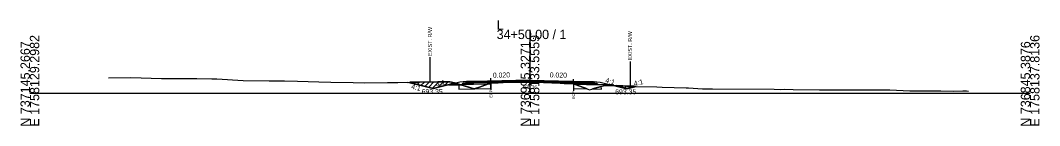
# Model space of a CAD drawing. Extents: x -26 to 4303, y -10 to 9577.
# Drawn here: x 1997.2 to 2302.8, y 4490.3 to 4521.9 of the extents above; entities that cross this region are included whole.
import ezdxf

# ---------------------------------------------------------------- set-up
doc = ezdxf.new("R2010")
doc.units = 0
for name, color, linetype in [('Default', 7, 'Continuous'), ('Exist CMT Pavement', 7, 'Continuous'), ('Old_Level_2', 7, 'Continuous'), ('Pattern 1', 7, 'Continuous'), ('Prop CMT Conc Surface', 7, 'Continuous'), ('Prop CMT Concrete Structures', 7, 'Continuous'), ('Prop CMT Pvmt Course 1', 7, 'Continuous'), ('Prop CMT Pvmt Course 1 CG', 7, 'Continuous'), ('Prop CMT Pvmt Course 1 Wedge', 7, 'Continuous'), ('Prop CMT Pvmt Course 2', 7, 'Continuous'), ('Prop CMT Pvmt Course 2 Wedge', 7, 'Continuous'), ('Prop CMT Pvmt Course 3', 7, 'Continuous'), ('Prop CMT Pvmt Surface', 7, 'Continuous'), ('Prop CMT Pvmt Surface Shoulder', 7, 'Continuous'), ('Prop CMT Pvmt Wedge Surface 1', 7, 'Continuous'), ('Prop CMT Pvmt Wedge Surface 2', 7, 'Continuous'), ('Prop CMT Pvmt Wedge Surface 3', 7, 'Continuous'), ('Prop CMT Shld Paved Course 1', 7, 'Continuous'), ('Prop CMT Shld Paved Course 2', 7, 'Continuous'), ('Prop CMT Shld Paved Course 3', 7, 'Continuous'), ('Prop CMT Slope Grass', 7, 'Continuous'), ('Prop CMT Subgrade Earthwork', 7, 'Continuous'), ('Prop Road Sect_ Recs - UC Shallow (Outline)', 7, 'Continuous'), ('Prop Shade Light', 7, 'Continuous'), ('Prop XS DDE Elevations', 7, 'Continuous'), ('Prop XS Ditch Standard Text', 7, 'Continuous'), ('Prop XS Hydro Elevations', 7, 'Continuous'), ('Prop XS SE Text', 7, 'Continuous'), ('Prop XS Side Slope Text', 7, 'Continuous'), ('Prop XS Wedging', 7, 'Continuous')]:
    doc.layers.add(name, color=color, linetype=linetype)

msp = doc.modelspace()

# ---------------------------------------------------------------- linework, layer by layer
at = {"layer": 'Exist CMT Pavement'}
for points in [[(2150, 4503.89), (2133, 4503.55)], [(2150, 4503.89), (2167, 4503.55)]]:
    msp.add_lwpolyline(points, dxfattribs=at)
at = {"layer": 'Old_Level_2'}
for p, q in [((2150, 4500), (2150, 4519.06)), ((2150, 4500), (2150, 4519.06)), ((2000, 4500), (2150, 4500)), ((2000, 4500), (2150, 4500)), ((2150, 4500), (2300, 4500)), ((2150, 4500), (2300, 4500))]:
    msp.add_line(p, q, dxfattribs=at)
at = {"layer": 'Pattern 1'}
for p, q in [((2113.99, 4503.27), (2114.01, 4503.29)), ((2115.12, 4502.99), (2115.45, 4503.32)), ((2116.25, 4502.71), (2116.89, 4503.34)), ((2117.38, 4502.42), (2118.32, 4503.36)), ((2118.51, 4502.14), (2119.76, 4503.38)), ((2119.65, 4501.86), (2121.19, 4503.4)), ((2120.78, 4501.57), (2122.62, 4503.42)), ((2122.51, 4501.9), (2124.05, 4503.43)), ((2124.4, 4502.37), (2125.47, 4503.44)), ((2126.15, 4502.71), (2126.71, 4503.27)), ((2127.6, 4502.74), (2127.85, 4502.99)), ((2176.2, 4502.22), (2176.27, 4502.29)), ((2177.33, 4501.94), (2177.63, 4502.24)), ((2178.46, 4501.65), (2178.99, 4502.18)), ((2179.98, 4501.77), (2180.34, 4502.13))]:
    msp.add_line(p, q, dxfattribs=at)
for points in [[(2121, 4501.52), (2125.72, 4502.7), (2128.66, 4502.76), (2127.39, 4503.12), (2125.95, 4503.44), (2122.32, 4503.42), (2116.49, 4503.34), (2113.92, 4503.29)], [(2137.78, 4502.94), (2138.29, 4503.12), (2138.29, 4502.95)], [(2175.84, 4502.31), (2179, 4501.52), (2181.28, 4502.09), (2179.79, 4502.15), (2177.85, 4502.23)]]:
    msp.add_lwpolyline(points, close=True, dxfattribs=at)
at = {"layer": 'Prop CMT Conc Surface'}
for points in [[(2138.29, 4503.41), (2133, 4503.3)], [(2133, 4503.3), (2133, 4503.09)], [(2133, 4503.09), (2138.29, 4503.2)], [(2138.29, 4503.2), (2138.29, 4503.41)], [(2163.07, 4503.17), (2163.07, 4503.38)], [(2163.07, 4503.38), (2167, 4503.3)], [(2167, 4503.09), (2163.07, 4503.17)], [(2167, 4503.3), (2167, 4503.09)]]:
    msp.add_lwpolyline(points, dxfattribs=at)
at = {"layer": 'Prop CMT Concrete Structures'}
for points in [[(2133, 4503.3), (2133, 4503.55)], [(2138.29, 4503.41), (2133, 4503.3)], [(2150, 4503.77), (2138.29, 4503.53)], [(2138.29, 4503.53), (2138.29, 4503.41)], [(2150, 4503.77), (2163.07, 4503.51)], [(2163.07, 4503.51), (2163.07, 4503.38)], [(2163.07, 4503.38), (2167, 4503.3)], [(2167, 4503.3), (2167, 4503.55)]]:
    msp.add_lwpolyline(points, dxfattribs=at)
at = {"layer": 'Prop CMT Pvmt Course 1'}
for points in [[(2138.29, 4503.2), (2133, 4503.09)], [(2133, 4503.09), (2133, 4502.76)], [(2133, 4502.76), (2138.29, 4502.87)], [(2138.29, 4502.87), (2138.29, 4503.2)], [(2163.07, 4503.17), (2167, 4503.09)], [(2163.07, 4502.84), (2163.07, 4503.17)], [(2167, 4502.76), (2163.07, 4502.84)], [(2167, 4503.09), (2167, 4502.76)]]:
    msp.add_lwpolyline(points, dxfattribs=at)
at = {"layer": 'Prop CMT Pvmt Course 1 Wedge'}
for points in [[(2138.29, 4503.2), (2138.39, 4503.2), (2138.75, 4503.21), (2138.88, 4503.21), (2139.95, 4503.23), (2140.5, 4503.24), (2141.57, 4503.27), (2142, 4503.27), (2144.07, 4503.32), (2144.43, 4503.32), (2146.58, 4503.37), (2146.86, 4503.37), (2149.08, 4503.42), (2149.13, 4503.42), (2149.55, 4503.43), (2149.78, 4503.43), (2150, 4503.43)], [(2150, 4503.36), (2149.78, 4503.36), (2149.55, 4503.35), (2149.13, 4503.34), (2149.08, 4503.34), (2146.86, 4503.33), (2146.58, 4503.33), (2144.43, 4503.29), (2144.07, 4503.29), (2142, 4503.21), (2141.57, 4503.2), (2140.5, 4503.18), (2139.95, 4503.17), (2138.88, 4503.15), (2138.75, 4503.16), (2138.39, 4503.16), (2138.29, 4503.12)], [(2138.29, 4503.12), (2138.29, 4503.2)], [(2150, 4503.43), (2150, 4503.36)], [(2150, 4503.43), (2150.44, 4503.43), (2151.28, 4503.41), (2151.55, 4503.4), (2151.58, 4503.4), (2151.72, 4503.4), (2154.08, 4503.35), (2154.15, 4503.35), (2156.58, 4503.3), (2156.59, 4503.3), (2156.84, 4503.3), (2159.02, 4503.25), (2159.08, 4503.25), (2160.22, 4503.23), (2160.74, 4503.22), (2161.92, 4503.2), (2163.03, 4503.17), (2163.06, 4503.17), (2163.07, 4503.17)], [(2163.07, 4502.79), (2163.06, 4502.8), (2163.03, 4502.8), (2161.92, 4502.92), (2160.74, 4502.96), (2160.22, 4502.96), (2159.08, 4503), (2159.02, 4503), (2156.84, 4503.12), (2156.59, 4503.13), (2156.58, 4503.13), (2154.15, 4503.24), (2154.08, 4503.25), (2151.72, 4503.32), (2151.58, 4503.33), (2151.55, 4503.33), (2151.28, 4503.34), (2150.44, 4503.36), (2150, 4503.36)], [(2163.07, 4503.17), (2163.07, 4502.79)]]:
    msp.add_lwpolyline(points, dxfattribs=at)
at = {"layer": 'Prop CMT Pvmt Course 2'}
for points in [[(2133, 4503.55), (2131, 4503.51), (2130.74, 4503.26)], [(2130.74, 4503.26), (2133, 4503.3)], [(2133, 4503.3), (2133, 4503.55)], [(2167, 4503.55), (2169, 4503.51), (2169.26, 4503.26)], [(2167, 4503.3), (2167, 4503.55)], [(2169.26, 4503.26), (2167, 4503.3)]]:
    msp.add_lwpolyline(points, dxfattribs=at)
at = {"layer": 'Prop CMT Pvmt Course 2 Wedge'}
for points in [[(2131, 4503.51), (2129, 4503.35), (2121, 4501.35), (2113.3, 4503.28)], [(2169, 4503.51), (2171, 4503.35), (2179, 4501.35), (2181.87, 4502.07)]]:
    msp.add_lwpolyline(points, dxfattribs=at)
at = {"layer": 'Prop CMT Pvmt Course 3'}
for points in [[(2133, 4503.3), (2130.74, 4503.26), (2130.53, 4503.05)], [(2130.53, 4503.05), (2133, 4503.09)], [(2133, 4503.09), (2133, 4503.3)], [(2167, 4503.3), (2169.26, 4503.26), (2169.47, 4503.05)], [(2167, 4503.09), (2167, 4503.3)], [(2169.47, 4503.05), (2167, 4503.09)]]:
    msp.add_lwpolyline(points, dxfattribs=at)
at = {"layer": 'Prop CMT Pvmt Surface'}
for points in [[(2150, 4503.64), (2133, 4503.3)], [(2133, 4503.3), (2133, 4503.55)], [(2150, 4503.64), (2167, 4503.3)], [(2167, 4503.3), (2167, 4503.55)]]:
    msp.add_lwpolyline(points, dxfattribs=at)
at = {"layer": 'Prop CMT Pvmt Surface Shoulder'}
for points in [[(2138.29, 4503.12), (2138.39, 4503.16), (2138.75, 4503.16), (2138.88, 4503.15), (2139.95, 4503.17), (2140.5, 4503.18), (2141.57, 4503.2), (2142, 4503.21), (2144.07, 4503.29), (2144.43, 4503.29), (2146.58, 4503.33), (2146.86, 4503.33), (2149.08, 4503.34), (2149.13, 4503.34), (2149.55, 4503.35), (2149.78, 4503.36), (2150, 4503.36)], [(2150, 4503.36), (2150.44, 4503.36), (2151.28, 4503.34), (2151.55, 4503.33), (2151.58, 4503.33), (2151.72, 4503.32), (2154.08, 4503.25), (2154.15, 4503.24), (2156.58, 4503.13), (2156.59, 4503.13), (2156.84, 4503.12), (2159.02, 4503), (2159.08, 4503), (2160.22, 4502.96), (2160.74, 4502.96), (2161.92, 4502.92), (2163.07, 4502.8)]]:
    msp.add_lwpolyline(points, dxfattribs=at)
at = {"layer": 'Prop CMT Pvmt Wedge Surface 1'}
for p, q in [((2138.29, 4502.74), (2133.02, 4502.64)), ((2163.07, 4502.71), (2166.98, 4502.64)), ((2133.02, 4502.64), (2125.53, 4502.49)), ((2166.98, 4502.64), (2174.47, 4502.49))]:
    msp.add_line(p, q, dxfattribs=at)
for points in [[(2138.29, 4502.74), (2138.29, 4503.12)], [(2163.07, 4502.8), (2163.07, 4502.71)]]:
    msp.add_lwpolyline(points, dxfattribs=at)
at = {"layer": 'Prop CMT Pvmt Wedge Surface 2'}
for points in [[(2138.29, 4503.53), (2138.39, 4503.54), (2138.75, 4503.54), (2138.88, 4503.55), (2139.95, 4503.57), (2140.5, 4503.58), (2141.57, 4503.6), (2142, 4503.61), (2144.07, 4503.65), (2144.43, 4503.66), (2146.58, 4503.7), (2146.86, 4503.7), (2149.08, 4503.75), (2149.13, 4503.75), (2149.55, 4503.76), (2149.78, 4503.76), (2150, 4503.77)], [(2150, 4503.64), (2149.78, 4503.64), (2149.55, 4503.63), (2149.13, 4503.63), (2149.08, 4503.62), (2146.86, 4503.58), (2146.58, 4503.57), (2144.43, 4503.53), (2144.07, 4503.52), (2142, 4503.48), (2141.57, 4503.47), (2140.5, 4503.45), (2139.95, 4503.44), (2138.88, 4503.42), (2138.75, 4503.42), (2138.39, 4503.41), (2138.29, 4503.41)], [(2138.29, 4503.41), (2138.29, 4503.53)], [(2150, 4503.77), (2150, 4503.64)], [(2150, 4503.77), (2150.44, 4503.76), (2151.28, 4503.74), (2151.55, 4503.74), (2151.58, 4503.74), (2151.72, 4503.73), (2154.08, 4503.69), (2154.15, 4503.68), (2156.58, 4503.64), (2156.59, 4503.64), (2156.84, 4503.63), (2159.02, 4503.59), (2159.08, 4503.59), (2160.22, 4503.56), (2160.74, 4503.55), (2161.92, 4503.53), (2163.03, 4503.51), (2163.06, 4503.51), (2163.07, 4503.51)], [(2163.07, 4503.38), (2163.06, 4503.38), (2163.03, 4503.38), (2161.92, 4503.4), (2160.74, 4503.43), (2160.22, 4503.44), (2159.08, 4503.46), (2159.02, 4503.46), (2156.84, 4503.51), (2156.59, 4503.51), (2156.58, 4503.51), (2154.15, 4503.56), (2154.08, 4503.56), (2151.72, 4503.61), (2151.58, 4503.61), (2151.55, 4503.61), (2151.28, 4503.62), (2150.44, 4503.63), (2150, 4503.64)], [(2163.07, 4503.51), (2163.07, 4503.38)]]:
    msp.add_lwpolyline(points, dxfattribs=at)
at = {"layer": 'Prop CMT Pvmt Wedge Surface 3'}
for points in [[(2138.29, 4503.41), (2138.39, 4503.41), (2138.75, 4503.42), (2138.88, 4503.42), (2139.95, 4503.44), (2140.5, 4503.45), (2141.57, 4503.47), (2142, 4503.48), (2144.07, 4503.52), (2144.43, 4503.53), (2146.58, 4503.57), (2146.86, 4503.58), (2149.08, 4503.62), (2149.13, 4503.63), (2149.55, 4503.63), (2149.78, 4503.64), (2150, 4503.64)], [(2150, 4503.43), (2149.78, 4503.43), (2149.55, 4503.43), (2149.13, 4503.42), (2149.08, 4503.42), (2146.86, 4503.37), (2146.58, 4503.37), (2144.43, 4503.32), (2144.07, 4503.32), (2142, 4503.27), (2141.57, 4503.27), (2140.5, 4503.24), (2139.95, 4503.23), (2138.88, 4503.21), (2138.75, 4503.21), (2138.39, 4503.2), (2138.29, 4503.2)], [(2138.29, 4503.2), (2138.29, 4503.41)], [(2150, 4503.64), (2150, 4503.43)], [(2150, 4503.64), (2150.44, 4503.63), (2151.28, 4503.62), (2151.55, 4503.61), (2151.58, 4503.61), (2151.72, 4503.61), (2154.08, 4503.56), (2154.15, 4503.56), (2156.58, 4503.51), (2156.59, 4503.51), (2156.84, 4503.51), (2159.02, 4503.46), (2159.08, 4503.46), (2160.22, 4503.44), (2160.74, 4503.43), (2161.92, 4503.4), (2163.03, 4503.38), (2163.06, 4503.38), (2163.07, 4503.38)], [(2163.07, 4503.17), (2163.06, 4503.17), (2163.03, 4503.17), (2161.92, 4503.2), (2160.74, 4503.22), (2160.22, 4503.23), (2159.08, 4503.25), (2159.02, 4503.25), (2156.84, 4503.3), (2156.59, 4503.3), (2156.58, 4503.3), (2154.15, 4503.35), (2154.08, 4503.35), (2151.72, 4503.4), (2151.58, 4503.4), (2151.55, 4503.4), (2151.28, 4503.41), (2150.44, 4503.43), (2150, 4503.43)], [(2163.07, 4503.38), (2163.07, 4503.17)]]:
    msp.add_lwpolyline(points, dxfattribs=at)
at = {"layer": 'Prop CMT Shld Paved Course 1'}
for points in [[(2133, 4503.09), (2133, 4503.55)], [(2150, 4503.43), (2133, 4503.09)], [(2150, 4503.43), (2167, 4503.09)], [(2167, 4503.09), (2167, 4503.55)]]:
    msp.add_lwpolyline(points, dxfattribs=at)
at = {"layer": 'Prop CMT Shld Paved Course 2'}
for points in [[(2133, 4503.55), (2131, 4503.51)], [(2167, 4503.55), (2169, 4503.51)]]:
    msp.add_lwpolyline(points, dxfattribs=at)
at = {"layer": 'Prop CMT Shld Paved Course 3'}
for points in [[(2150, 4503.89), (2133, 4503.55)], [(2133, 4503.55), (2133, 4503.3)], [(2133, 4503.3), (2138.29, 4503.41)], [(2138.29, 4503.53), (2150, 4503.77)], [(2138.29, 4503.41), (2138.29, 4503.53)], [(2150, 4503.64), (2150, 4503.89)], [(2150, 4503.89), (2167, 4503.55)], [(2150, 4503.77), (2150, 4503.64), (2150, 4503.64)], [(2163.07, 4503.51), (2150, 4503.77)], [(2163.07, 4503.38), (2163.07, 4503.51)], [(2167, 4503.3), (2163.07, 4503.38)], [(2167, 4503.55), (2167, 4503.3)]]:
    msp.add_lwpolyline(points, dxfattribs=at)
at = {"layer": 'Prop CMT Slope Grass'}
msp.add_lwpolyline([(2023.61, 4504.67), (2030.28, 4504.73), (2039.45, 4504.47), (2040.91, 4504.45), (2050.08, 4504.42), (2054.54, 4504.32), (2056.03, 4504.34), (2063.97, 4503.8), (2071.73, 4503.73), (2076.36, 4503.69), (2080.31, 4503.67), (2086.66, 4503.47), (2090.31, 4503.37), (2096.96, 4503.27), (2100.32, 4503.18), (2107.26, 4503.27), (2110.32, 4503.22), (2120.38, 4503.41), (2124.24, 4503.43), (2125.95, 4503.44), (2127.4, 4503.11), (2133.29, 4501.38), (2134.82, 4501.87), (2138.39, 4503.16), (2138.88, 4503.15), (2139.95, 4503.17), (2140.5, 4503.18), (2141.57, 4503.2), (2142, 4503.21), (2144.07, 4503.29), (2144.43, 4503.29), (2146.86, 4503.33), (2149.13, 4503.34), (2150, 4503.36), (2150.44, 4503.36), (2151.72, 4503.32), (2154.15, 4503.24), (2156.84, 4503.12), (2159.08, 4503), (2160.22, 4502.96), (2160.74, 4502.96), (2161.92, 4502.92), (2163.06, 4502.8), (2167.39, 4501.26), (2167.89, 4501.07), (2172.07, 4502.22), (2174.21, 4502.38), (2181.5, 4502.08), (2188.01, 4501.89), (2189.63, 4501.85), (2196.8, 4501.65), (2197.56, 4501.65), (2201.69, 4501.33), (2202.02, 4501.33), (2204.15, 4501.36), (2204.74, 4501.36), (2223.22, 4501.2), (2225.23, 4501.18), (2226.45, 4501.21), (2228.88, 4501.15), (2236.86, 4501.06), (2243.94, 4501.05), (2246.67, 4501.04), (2256.6, 4501.02), (2257.94, 4500.99), (2261.93, 4500.83), (2263.96, 4500.74), (2269.06, 4500.76), (2273.19, 4500.77), (2277.13, 4500.65), (2279.84, 4500.7), (2280.93, 4500.69), (2281.47, 4500.68)], dxfattribs=at)
at = {"layer": 'Prop CMT Subgrade Earthwork'}
for points in [[(2133, 4503.09), (2130.53, 4503.05), (2130.03, 4503.04), (2129.69, 4502.69)], [(2129.69, 4502.69), (2133, 4502.76)], [(2133, 4502.76), (2133, 4503.09)], [(2167, 4503.09), (2169.47, 4503.05), (2169.97, 4503.04), (2170.31, 4502.69)], [(2167, 4502.76), (2167, 4503.09)], [(2170.31, 4502.69), (2167, 4502.76)]]:
    msp.add_lwpolyline(points, dxfattribs=at)
at = {"layer": 'Prop Road Sect_ Recs - UC Shallow (Outline)'}
for points in [[(2128.66, 4502.74), (2128.67, 4501.26), (2138.29, 4501.45), (2138.29, 4502.95), (2137.78, 4502.94), (2134.82, 4501.87), (2133.29, 4501.38)], [(2163.07, 4501.42), (2167.14, 4501.34), (2164.69, 4502.22), (2163.07, 4502.79)], [(2171.4, 4501.26), (2171.39, 4502.04), (2168.9, 4501.35), (2168.76, 4501.31)]]:
    msp.add_lwpolyline(points, close=True, dxfattribs=at)
at = {"layer": 'Prop Shade Light'}
for p, q in [((2128.66, 4502.74), (2128.67, 4501.26)), ((2138.29, 4502.95), (2137.78, 4502.94)), ((2137.78, 4502.94), (2137.78, 4502.94)), ((2138.29, 4501.45), (2138.29, 4502.95)), ((2163.07, 4502.79), (2163.07, 4501.42)), ((2167.14, 4501.34), (2163.07, 4502.79)), ((2128.67, 4501.26), (2138.29, 4501.45)), ((2163.07, 4501.42), (2167.14, 4501.34)), ((2171.39, 4502.04), (2168.76, 4501.31)), ((2168.76, 4501.31), (2171.4, 4501.26)), ((2171.4, 4501.26), (2171.39, 4502.04))]:
    msp.add_line(p, q, dxfattribs=at)
msp.add_lwpolyline([(2137.78, 4502.94), (2134.82, 4501.87), (2133.29, 4501.38), (2128.66, 4502.74)], dxfattribs=at)
at = {"layer": 'Prop XS DDE Elevations'}
for points in [[(2125.95, 4503.44), (2127.4, 4503.11), (2127.7, 4503.03), (2125.53, 4502.49), (2121, 4501.35), (2113.3, 4503.28), (2120.38, 4503.41), (2124.24, 4503.43)], [(2127.7, 4503.03), (2125.53, 4502.49), (2129.28, 4502.56)], [(2134.82, 4501.87), (2137.17, 4502.72), (2133.02, 4502.64), (2129.28, 4502.56), (2133.29, 4501.38)], [(2137.17, 4502.72), (2138.29, 4503.12), (2138.29, 4502.74)], [(2146.86, 4503.33), (2149.13, 4503.34), (2149.08, 4503.34)], [(2149.13, 4503.34), (2149.69, 4503.35), (2149.55, 4503.35)], [(2149.69, 4503.35), (2150, 4503.36), (2149.78, 4503.36)], [(2151.55, 4503.33), (2151.58, 4503.33), (2150.44, 4503.36), (2151.28, 4503.34)], [(2151.72, 4503.32), (2154.08, 4503.25), (2154.15, 4503.24)], [(2154.15, 4503.24), (2156.58, 4503.13), (2156.84, 4503.12)], [(2161.92, 4502.92), (2163.07, 4502.8), (2163.06, 4502.8)], [(2163.07, 4502.8), (2163.07, 4502.71), (2163.3, 4502.71)], [(2172.07, 4502.22), (2174.21, 4502.38), (2175.04, 4502.34), (2174.47, 4502.49), (2166.98, 4502.64), (2163.3, 4502.71), (2167.39, 4501.26), (2167.89, 4501.07)], [(2179, 4501.35), (2181.87, 4502.07), (2181.5, 4502.08), (2175.04, 4502.34)]]:
    msp.add_lwpolyline(points, close=True, dxfattribs=at)
at = {"layer": 'Prop XS Ditch Standard Text'}
for p, q in [((2120, 4510.8), (2120, 4503.4)), ((2180, 4509.54), (2180, 4502.14)), ((2138.29, 4503.12), (2138.29, 4501.07)), ((2163.07, 4502.79), (2163.07, 4500.74))]:
    msp.add_line(p, q, dxfattribs=at)
at = {"layer": 'Prop XS Wedging'}
for p, q in [((2138.29, 4503.12), (2138.29, 4504.57)), ((2138.29, 4503.41), (2150, 4503.64)), ((2138.29, 4503.53), (2138.29, 4503.41)), ((2138.29, 4503.41), (2138.29, 4503.12)), ((2138.29, 4503.12), (2138.39, 4503.16)), ((2140.5, 4503.18), (2141.57, 4503.2)), ((2144.07, 4503.29), (2144.43, 4503.29)), ((2144.43, 4503.29), (2146.58, 4503.33)), ((2150, 4503.64), (2150, 4503.64)), ((2150, 4503.64), (2150, 4503.64)), ((2150, 4503.64), (2163.07, 4503.38)), ((2150, 4503.64), (2150, 4503.64)), ((2163.07, 4503.38), (2150, 4503.64)), ((2150, 4503.36), (2150.44, 4503.36)), ((2163.07, 4502.79), (2163.07, 4504.28)), ((2163.07, 4503.38), (2163.07, 4503.51)), ((2163.07, 4502.8), (2163.07, 4503.38))]:
    msp.add_line(p, q, dxfattribs=at)
for points in [[(2150, 4503.77), (2133, 4503.43)], [(2150, 4503.64), (2133, 4503.3)], [(2150, 4503.77), (2150, 4503.77), (2138.29, 4503.53)], [(2150, 4503.64), (2150, 4503.64), (2138.29, 4503.41)], [(2138.39, 4503.16), (2138.75, 4503.16), (2138.88, 4503.15)], [(2138.88, 4503.15), (2139.95, 4503.17), (2140.5, 4503.18)], [(2141.57, 4503.2), (2142, 4503.21), (2144.07, 4503.29)], [(2146.58, 4503.33), (2146.86, 4503.33), (2149.08, 4503.34), (2149.13, 4503.34)], [(2149.13, 4503.34), (2149.55, 4503.35), (2149.69, 4503.35)], [(2149.69, 4503.35), (2149.78, 4503.36), (2150, 4503.36)], [(2150, 4503.77), (2167, 4503.43)], [(2163.07, 4503.51), (2150, 4503.77), (2150, 4503.77)], [(2150, 4503.64), (2167, 4503.3)], [(2150, 4503.64), (2150, 4503.64)], [(2150, 4503.64), (2150, 4503.64)], [(2150.44, 4503.36), (2151.28, 4503.34), (2151.55, 4503.33), (2151.57, 4503.33)], [(2151.57, 4503.33), (2151.58, 4503.33), (2151.72, 4503.32)], [(2151.72, 4503.32), (2154.08, 4503.25), (2154.15, 4503.24), (2156.58, 4503.13), (2156.59, 4503.13), (2156.84, 4503.12)], [(2156.84, 4503.12), (2159.02, 4503.01), (2159.08, 4503)], [(2159.08, 4503), (2160.22, 4502.96), (2160.74, 4502.96), (2161.92, 4502.92), (2163.07, 4502.8)], [(2163.07, 4502.8), (2163.07, 4502.8)]]:
    msp.add_lwpolyline(points, dxfattribs=at)

# ---------------------------------------------------------------- texts
at = {"layer": 'Default'}
msp.add_text('-', height=0.0001, dxfattribs=at).set_placement((2000, 4500))
at = {"layer": 'Old_Level_2'}
for s, p in [('L', (2140, 4519.06)), ('L', (2140, 4519.06)), ('34+50.00 / 1', (2140, 4516.26)), ('34+50.00 / 1', (2140, 4516.26))]:
    msp.add_text(s, height=2.8, dxfattribs=at).set_placement(p)
for s, p in [('N 737145.2667', (2000, 4490)), ('N 737145.2667', (2000, 4490)), ('E 1758129.2982', (2002.8, 4490)), ('E 1758129.2982', (2002.8, 4490)), ('N 736995.3271', (2150, 4490)), ('N 736995.3271', (2150, 4490)), ('E 1758133.5559', (2152.8, 4490)), ('E 1758133.5559', (2152.8, 4490)), ('N 736845.3876', (2300, 4490)), ('N 736845.3876', (2300, 4490)), ('E 1758137.8136', (2302.8, 4490)), ('E 1758137.8136', (2302.8, 4490))]:
    msp.add_text(s, height=2.8, rotation=90, dxfattribs=at).set_placement(p)
at = {"layer": 'Prop CMT Pvmt Course 1 CG'}
msp.add_text('695.36', height=1, dxfattribs=at).set_placement((2147.86, 4501.36))
at = {"layer": 'Prop XS Ditch Standard Text'}
for s, height, p in [('EXIST. R/W', 1.181, (2120.59, 4511.11)), ('EXIST. R/W', 1.181, (2180.59, 4509.84)), ('EOP', 0.787, (2138.68, 4498.68)), ('EOP', 0.787, (2163.47, 4498.34))]:
    msp.add_text(s, height=height, rotation=90, dxfattribs=at).set_placement(p)
at = {"layer": 'Prop XS Hydro Elevations'}
for p in [(2117.5, 4499.77), (2175.54, 4499.71)]:
    msp.add_text('693.35', height=1.5, dxfattribs=at).set_placement(p)
at = {"layer": 'Prop XS SE Text'}
for rotation, p in [(1.1458, (2138.86, 4504.67)), (358.8542, (2155.9, 4504.77))]:
    msp.add_text('0.020', height=1.5, rotation=rotation, dxfattribs=at).set_placement(p)
at = {"layer": 'Prop XS Side Slope Text'}
for rotation, p in [(14.0362, (2121.96, 4501.92)), (345.9638, (2172.48, 4503.23)), (14.0362, (2181.32, 4502.11)), (345.9638, (2114.26, 4501.37))]:
    msp.add_text('4:1', height=1.5, rotation=rotation, dxfattribs=at).set_placement(p)

doc.saveas('drawing.dxf')
